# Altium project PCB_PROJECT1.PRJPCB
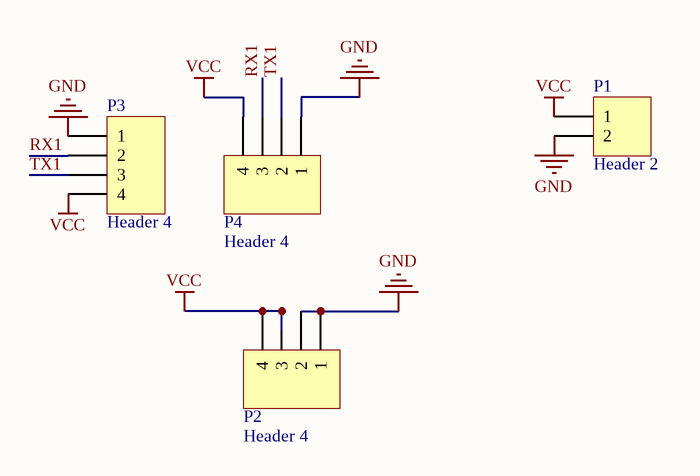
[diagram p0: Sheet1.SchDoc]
1 sheet, 4 parts. Net scope: global (net labels, ports and power ports of the same name join across sheets).
Board file: PCB2.PcbDoc

## Sheet Sheet1.SchDoc
size A4

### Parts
P1  Header 2  [HDR1X2]
P2  Header 4  [HDR1X4]
P3  Header 4  [HDR1X4]
P4  Header 4  [HDR1X4]

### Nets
GND: P1.2 P2.1 P2.2 P3.1 P4.1
VCC: P1.1 P2.3 P2.4 P3.4 P4.4
RX1: P3.2 P4.3
TX1: P3.3 P4.2

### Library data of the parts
P1 = Header 2: Header, 2-Pin
P2-P4 = Header 4: Header, 4-Pin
